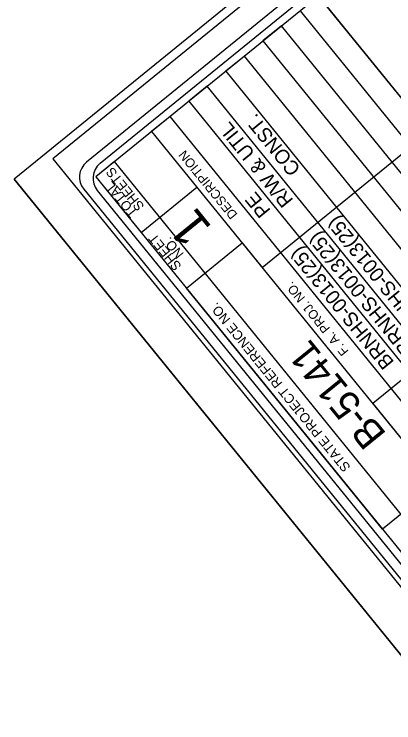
# Model space of a CAD drawing. Extents: x 2596486 to 2602076, y 851390 to 856110.
# Drawn here: x 2596486 to 2596823, y 853129 to 853758 of the extents above; entities that cross this region are included whole.
import ezdxf

# ---------------------------------------------------------------- set-up
doc = ezdxf.new("R2010")
doc.units = 0
for name, color, linetype in [('Old_Level_12', 7, 'Continuous'), ('Sheet Cutting Line CELL', 7, 'Continuous'), ('Sheet Data Field CELL', 7, 'Continuous'), ('Sheet Plot Border Inside CELL', 7, 'Continuous'), ('Sheet Plot Border Outside CELL', 7, 'Continuous'), ('Sheet Title CELL', 7, 'Continuous')]:
    doc.layers.add(name, color=color, linetype=linetype)

msp = doc.modelspace()

# ---------------------------------------------------------------- linework, layer by layer
at = {"layer": 'Old_Level_12'}
msp.add_lwpolyline([(2596756.38, 853774.59), (2597051.2, 853411.85), (2597147.31, 853489.97), (2596852.49, 853852.71)], close=True, dxfattribs=at)
at = {"layer": 'Sheet Cutting Line CELL'}
msp.add_line((2598291.52, 851390.23), (2596485.91, 853611.8), dxfattribs=at)
at = {"layer": 'Sheet Plot Border Inside CELL'}
msp.add_lwpolyline([(2599699.12, 852562.74), (2597912.27, 854761.23), (2596520.36, 853629.94), (2598307.2, 851431.45)], close=True, dxfattribs=at)
at = {"layer": 'Sheet Plot Border Outside CELL'}
msp.add_lwpolyline([(2596485.91, 853611.8), (2598291.52, 851390.23), (2599742.65, 852569.65), (2597937.05, 854791.22)], close=True, dxfattribs=at)
at = {"layer": 'Sheet Title CELL'}
for points in [[(2597909.1, 854731.27), (2596550.31, 853626.9)], [(2597663.83, 854520.97), (2596562.26, 853625.66)], [(2596953.12, 853532.91), (2596804.71, 853412.29), (2596862.77, 853340.85), (2596813.28, 853300.63), (2596639.05, 853515.03), (2596688.52, 853555.21), (2596706.42, 853533.18), (2596854.84, 853653.8), (2596756.51, 853774.78), (2596558.63, 853613.94), (2596598.84, 853564.47), (2596648.29, 853604.7)], [(2597051.37, 853411.99), (2596756.51, 853774.78)], [(2596740.04, 853761.39), (2597034.88, 853398.59)], [(2597018.41, 853385.2), (2596723.55, 853747.99), (2596707.06, 853734.58), (2597001.9, 853371.81)], [(2596985.41, 853358.38), (2596690.55, 853721.17), (2596674.06, 853707.76), (2596968.92, 853344.98)], [(2596952.45, 853331.59), (2596657.57, 853694.36), (2596641.1, 853680.97), (2596935.96, 853318.18)], [(2596919.47, 853304.78), (2596624.61, 853667.57), (2596608.1, 853654.15), (2596902.96, 853291.37)], [(2596869.98, 853264.56), (2596575.12, 853627.35), (2596558.63, 853613.94), (2596853.5, 853251.17)], [(2596547.83, 853603.01), (2598134.72, 851650.5)], [(2596559.8, 853601.75), (2598082.33, 851728.47)]]:
    msp.add_lwpolyline(points, dxfattribs=at)
for centre in [(2596560.96, 853613.66), (2596572.91, 853612.42)]:
    msp.add_arc(centre, 17, 129.10281, 219.10281, dxfattribs=at)

# ---------------------------------------------------------------- texts
at = {"layer": 'Sheet Data Field CELL'}
for s, height, p in [('CONST.', 12.75, (2596741.19, 853621.1)), ('R/W & UTIL', 12.75, (2596734.51, 853593.09)), ('PE        ', 12.75, (2596714.38, 853583.93)), ('BRNHS-0013(25)', 12.75, (2596857.21, 853476.6)), ('BRNHS-0013(25)', 12.75, (2596840.59, 853462.61)), ('BRNHS-0013(25)', 12.75, (2596824.1, 853449.21)), ('B-5141    ', 25.5, (2596817.49, 853385.23))]:
    msp.add_text(s, height=height, rotation=129.10281, dxfattribs=at).set_placement(p)
at = {"layer": 'Sheet Title CELL'}
for s, height, p in [('DESCRIPTION', 8.16, (2596684.85, 853580.38)), ('SHEETS', 8.5, (2596602.05, 853587.87)), ('TOTAL', 8.5, (2596595.82, 853582.07)), ('1', 32.89, (2596662.48, 853568.78)), ('SHEET', 8.5, (2596635.11, 853534.7)), ('NO.', 8.5, (2596637.18, 853545.47)), ('F. A. PROJ. NO.', 8.16, (2596783.58, 853458.86)), ('STATE PROJECT REFERENCE NO.', 8.4997, (2596785.35, 853355.92))]:
    msp.add_text(s, height=height, rotation=129.10281, dxfattribs=at).set_placement(p)

doc.saveas('drawing.dxf')
